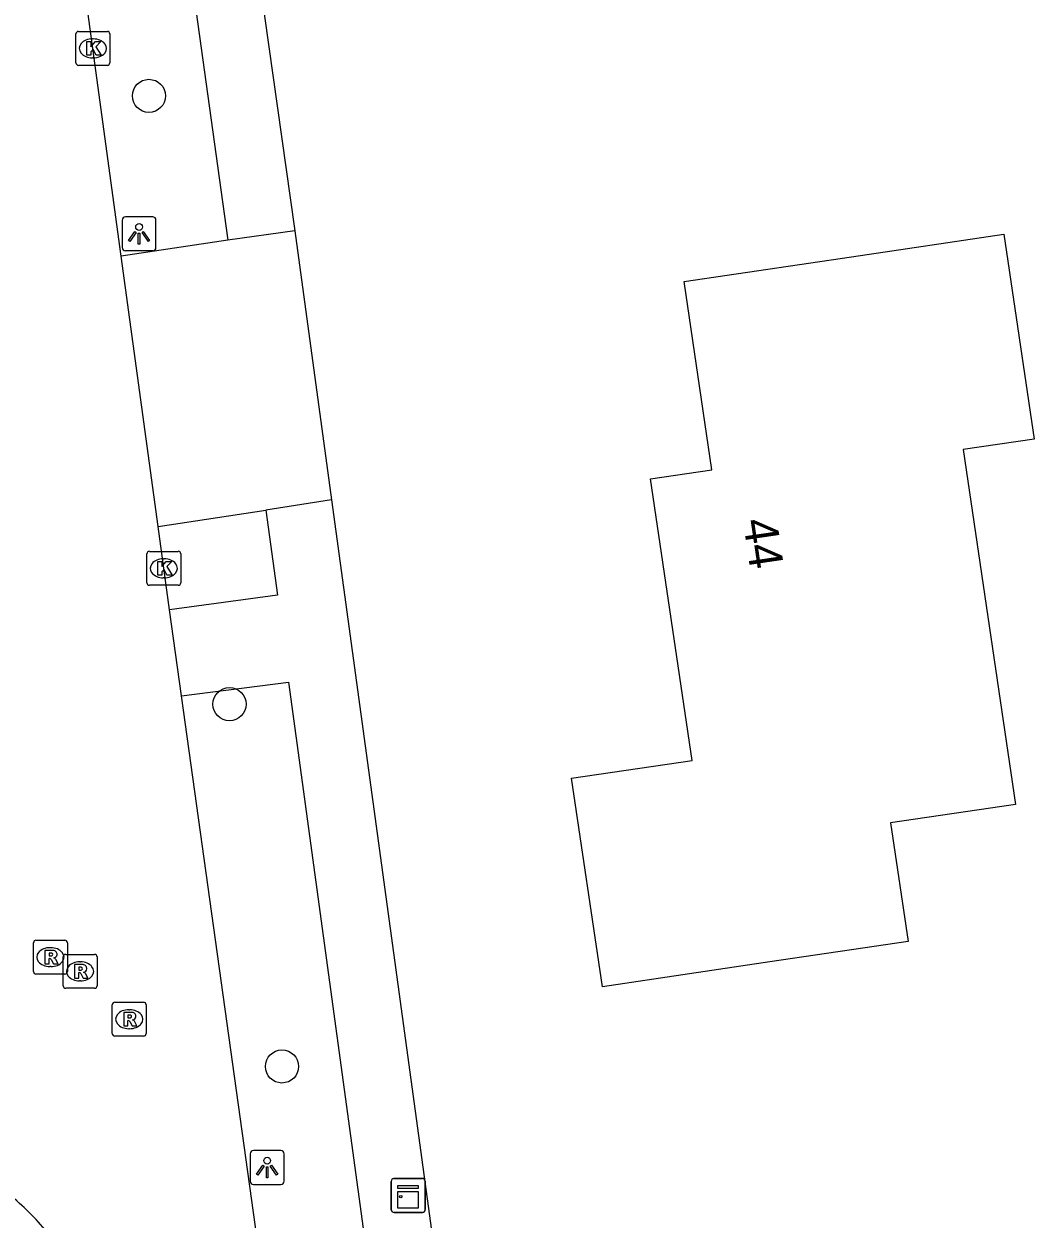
# Model space of a CAD drawing. Extents: x 162722 to 165099, y 384721 to 386283.
# Drawn here: x 164101.93 to 164131.75, y 385084.27 to 385119.55 of the extents above; entities that cross this region are included whole.
import ezdxf

# ---------------------------------------------------------------- set-up
doc = ezdxf.new("R2010")
doc.units = 0
for name, color, linetype in [('IMGEO_Boom', 7, 'Continuous'), ('IMGEO_Kast', 7, 'Continuous'), ('IMGEO_Kolk', 7, 'Continuous'), ('IMGEO_Lichtpunt', 7, 'Continuous'), ('IMGEO_Pand', 7, 'Continuous'), ('IMGEO_Pand_nummerreeks', 7, 'Continuous'), ('IMGEO_Rijbaan_lokaal_open', 7, 'Continuous'), ('IMGEO_Rioolput', 7, 'Continuous'), ('IMGEO_Voetpad_open', 7, 'Continuous')]:
    doc.layers.add(name, color=color, linetype=linetype)

msp = doc.modelspace()

# ---------------------------------------------------------------- linework, layer by layer
at = {"layer": 'IMGEO_Boom'}
for centre in [(164105.622, 385117.421), (164108, 385099.47), (164109.549, 385088.779)]:
    msp.add_circle(centre, 0.489, dxfattribs=at)
at = {"layer": 'IMGEO_Kast'}
for p, q in [((164112.775, 385084.546), (164112.775, 385085.387)), ((164112.775, 385085.387), (164112.775, 385084.546)), ((164112.85, 385085.471), (164113.691, 385085.471)), ((164113.691, 385085.471), (164112.85, 385085.471)), ((164113.775, 385085.396), (164113.775, 385084.555)), ((164113.775, 385084.555), (164113.775, 385085.396)), ((164113.7, 385084.471), (164112.859, 385084.471)), ((164112.859, 385084.471), (164113.7, 385084.471))]:
    msp.add_line(p, q, dxfattribs=at)
for points in [[(164112.97, 385085.261), (164113.57, 385085.261), (164113.57, 385085.176), (164112.97, 385085.176), (164112.97, 385085.261)], [(164112.97, 385085.086), (164113.57, 385085.086), (164113.57, 385084.597), (164112.97, 385084.597), (164112.97, 385085.086)]]:
    msp.add_lwpolyline(points, dxfattribs=at)
msp.add_circle((164113.054, 385084.935), 0.0377, dxfattribs=at)
for centre, start, end in [((164112.853, 385085.393), 92.4484, 184.2845), ((164112.853, 385085.393), 92.4484, 184.2845), ((164113.697, 385085.393), 2.4484, 94.2845), ((164113.697, 385085.393), 2.4484, 94.2845), ((164112.853, 385084.549), 182.4484, 274.2845), ((164112.853, 385084.549), 182.4484, 274.2845), ((164113.697, 385084.549), 272.4484, 4.2845), ((164113.697, 385084.549), 272.4484, 4.2845)]:
    msp.add_arc(centre, 0.0779, start, end, dxfattribs=at)
at = {"layer": 'IMGEO_Kolk'}
for p, q in [((164103.467, 385118.397), (164103.467, 385119.249)), ((164103.542, 385119.323), (164104.394, 385119.323)), ((164104.468, 385119.249), (164104.468, 385118.397)), ((164103.955, 385119.103), (164103.98, 385119.103)), ((164103.978, 385118.543), (164103.953, 385118.543)), ((164104.394, 385118.323), (164103.542, 385118.323)), ((164105.56, 385103.054), (164105.56, 385103.906)), ((164105.635, 385103.98), (164106.487, 385103.98)), ((164106.048, 385103.76), (164106.073, 385103.76)), ((164106.561, 385103.906), (164106.561, 385103.054)), ((164106.487, 385102.98), (164105.635, 385102.98)), ((164106.071, 385103.2), (164106.046, 385103.2))]:
    msp.add_line(p, q, dxfattribs=at)
for points in [[(164103.467, 385118.397), (164103.467, 385119.249)], [(164103.542, 385119.323), (164104.394, 385119.323)], [(164104.468, 385119.249), (164104.468, 385118.397)], [(164103.788, 385119.023), (164103.911, 385119.023), (164103.911, 385118.872), (164104.041, 385119.023), (164104.205, 385119.023), (164104.059, 385118.872), (164104.212, 385118.623), (164104.06, 385118.623), (164103.975, 385118.787), (164103.911, 385118.72), (164103.911, 385118.623), (164103.788, 385118.623), (164103.788, 385119.023)], [(164104.394, 385118.323), (164103.542, 385118.323)], [(164105.56, 385103.054), (164105.56, 385103.906)], [(164105.635, 385103.98), (164106.487, 385103.98)], [(164105.881, 385103.68), (164106.004, 385103.68), (164106.004, 385103.529), (164106.134, 385103.68), (164106.298, 385103.68), (164106.152, 385103.529), (164106.305, 385103.28), (164106.153, 385103.28), (164106.068, 385103.444), (164106.004, 385103.377), (164106.004, 385103.28), (164105.881, 385103.28), (164105.881, 385103.68)], [(164106.561, 385103.906), (164106.561, 385103.054)], [(164106.487, 385102.98), (164105.635, 385102.98)]]:
    msp.add_lwpolyline(points, dxfattribs=at)
for centre, start, end in [((164103.544, 385119.247), 91.552, 178.448), ((164103.544, 385119.247), 91.552, 178.448), ((164104.392, 385119.247), 1.552, 88.448), ((164104.392, 385119.247), 1.552, 88.448), ((164103.544, 385118.399), 181.552, 268.448), ((164103.544, 385118.399), 181.552, 268.448), ((164104.392, 385118.399), 271.552, 358.448), ((164104.392, 385118.399), 271.552, 358.448), ((164105.637, 385103.904), 91.552, 178.448), ((164105.637, 385103.904), 91.552, 178.448), ((164106.485, 385103.904), 1.552, 88.448), ((164106.485, 385103.904), 1.552, 88.448), ((164105.637, 385103.056), 181.552, 268.448), ((164105.637, 385103.056), 181.552, 268.448), ((164106.485, 385103.056), 271.552, 358.448), ((164106.485, 385103.056), 271.552, 358.448)]:
    msp.add_arc(centre, 0.0765, start, end, dxfattribs=at)
for centre, major_axis, ratio, start_param, end_param in [((164103.954, 385118.823), (-0.387, 0.002), 0.722429, 4.712389, 7.853982), ((164103.979, 385118.823), (-0.39, 0.002), 0.717154, 1.570796, 4.712389), ((164106.047, 385103.48), (-0.387, 0.002), 0.722429, 4.712389, 7.853982), ((164106.072, 385103.48), (-0.39, 0.002), 0.717154, 1.570796, 4.712389)]:
    msp.add_ellipse(centre, major_axis=major_axis, ratio=ratio, start_param=start_param, end_param=end_param, dxfattribs=at)
at = {"layer": 'IMGEO_Lichtpunt'}
for p, q in [((164104.832, 385113.755), (164104.832, 385112.948)), ((164104.832, 385113.755), (164104.832, 385112.948)), ((164105.734, 385113.85), (164104.926, 385113.85)), ((164105.734, 385113.85), (164104.926, 385113.85)), ((164105.828, 385112.948), (164105.828, 385113.755)), ((164105.828, 385112.948), (164105.828, 385113.755)), ((164104.926, 385112.854), (164105.734, 385112.854)), ((164104.926, 385112.854), (164105.734, 385112.854)), ((164108.613, 385086.2), (164108.613, 385085.393)), ((164108.613, 385086.2), (164108.613, 385085.393)), ((164109.515, 385086.295), (164108.707, 385086.295)), ((164109.515, 385086.295), (164108.707, 385086.295)), ((164109.609, 385085.393), (164109.609, 385086.2)), ((164109.609, 385085.393), (164109.609, 385086.2)), ((164108.707, 385085.299), (164109.515, 385085.299)), ((164108.707, 385085.299), (164109.515, 385085.299))]:
    msp.add_line(p, q, dxfattribs=at)
for points in [[(164105.206, 385113.419), (164105.245, 385113.391), (164105.057, 385113.129), (164105.019, 385113.156), (164105.206, 385113.419)], [(164105.308, 385113.371), (164105.355, 385113.371), (164105.355, 385113.049), (164105.308, 385113.049), (164105.308, 385113.371)], [(164105.418, 385113.391), (164105.456, 385113.418), (164105.643, 385113.156), (164105.604, 385113.128), (164105.418, 385113.391)], [(164108.987, 385085.864), (164109.026, 385085.836), (164108.838, 385085.574), (164108.8, 385085.601), (164108.987, 385085.864)], [(164109.089, 385085.816), (164109.136, 385085.816), (164109.136, 385085.494), (164109.089, 385085.494), (164109.089, 385085.816)], [(164109.199, 385085.836), (164109.237, 385085.863), (164109.424, 385085.601), (164109.385, 385085.573), (164109.199, 385085.836)]]:
    msp.add_lwpolyline(points, dxfattribs=at)
for centre in [(164105.331, 385113.553), (164109.112, 385085.998)]:
    msp.add_circle(centre, 0.0994, dxfattribs=at)
for centre, start, end in [((164104.926, 385113.755), 90, 180), ((164104.926, 385113.755), 90, 180), ((164105.734, 385113.755), 0, 90), ((164105.734, 385113.755), 0, 90), ((164104.926, 385112.948), 180, 270), ((164104.926, 385112.948), 180, 270), ((164105.734, 385112.948), 270, 0), ((164105.734, 385112.948), 270, 360), ((164108.707, 385086.2), 90, 180), ((164108.707, 385086.2), 90, 180), ((164109.515, 385086.2), 0, 90), ((164109.515, 385086.2), 0, 90), ((164108.707, 385085.393), 180, 270), ((164108.707, 385085.393), 180, 270), ((164109.515, 385085.393), 270, 0), ((164109.515, 385085.393), 270, 360)]:
    msp.add_arc(centre, 0.0946, start, end, dxfattribs=at)
at = {"layer": 'IMGEO_Pand'}
msp.add_lwpolyline([(164118.098, 385097.284), (164121.653, 385097.809), (164120.426, 385106.121), (164122.237, 385106.388), (164121.417, 385111.942), (164126.364, 385112.672), (164130.858, 385113.336), (164131.75, 385107.292), (164129.656, 385106.983), (164131.203, 385096.51), (164127.512, 385095.965), (164128.029, 385092.464), (164123.953, 385091.862), (164119.006, 385091.132), (164118.098, 385097.284)], dxfattribs=at)
at = {"layer": 'IMGEO_Rijbaan_lokaal_open'}
for points in [[(164104.802, 385112.693), (164102.809, 385127.339)], [(164105.897, 385104.717), (164104.802, 385112.693)], [(164106.23, 385102.25), (164106.061, 385103.48), (164105.897, 385104.717)], [(164106.583, 385099.714), (164106.23, 385102.25)], [(164109.468, 385078.814), (164109.099, 385081.644), (164106.583, 385099.714)]]:
    msp.add_lwpolyline(points, dxfattribs=at)
msp.add_arc((164095.292, 385077.685), 9.601, 39.0574, 48.5439, dxfattribs=at)
at = {"layer": 'IMGEO_Rioolput'}
for p, q in [((164102.213, 385091.578), (164102.213, 385092.43)), ((164102.288, 385092.504), (164103.14, 385092.504)), ((164103.214, 385092.43), (164103.214, 385091.578)), ((164102.701, 385092.284), (164102.726, 385092.284)), ((164103.165, 385092.085), (164104.017, 385092.085)), ((164102.724, 385091.724), (164102.699, 385091.724)), ((164103.09, 385091.159), (164103.09, 385092.011)), ((164103.578, 385091.865), (164103.603, 385091.865)), ((164104.091, 385092.011), (164104.091, 385091.159)), ((164103.14, 385091.504), (164102.288, 385091.504)), ((164104.017, 385091.085), (164103.165, 385091.085)), ((164103.601, 385091.305), (164103.576, 385091.305)), ((164104.614, 385090.673), (164105.466, 385090.673)), ((164104.539, 385089.747), (164104.539, 385090.599)), ((164105.027, 385090.453), (164105.052, 385090.453)), ((164105.54, 385090.599), (164105.54, 385089.747)), ((164105.466, 385089.673), (164104.614, 385089.673)), ((164105.05, 385089.893), (164105.025, 385089.893))]:
    msp.add_line(p, q, dxfattribs=at)
for points in [[(164102.213, 385091.578), (164102.213, 385092.43)], [(164102.288, 385092.504), (164103.14, 385092.504)], [(164103.214, 385092.43), (164103.214, 385091.578)], [(164102.802, 385092.202), (164102.55, 385092.204), (164102.55, 385091.804)], [(164102.728, 385092.123), (164102.674, 385092.123), (164102.674, 385092.042)], [(164102.674, 385092.042), (164102.726, 385092.042)], [(164103.165, 385092.085), (164104.017, 385092.085)], [(164102.55, 385091.804), (164102.674, 385091.804), (164102.674, 385091.966), (164102.685, 385091.966)], [(164102.732, 385091.937), (164102.803, 385091.804), (164102.943, 385091.804), (164102.878, 385091.93)], [(164103.09, 385091.159), (164103.09, 385092.011)], [(164103.679, 385091.783), (164103.427, 385091.785), (164103.427, 385091.385)], [(164103.605, 385091.704), (164103.551, 385091.704), (164103.551, 385091.623)], [(164104.091, 385092.011), (164104.091, 385091.159)], [(164103.14, 385091.504), (164102.288, 385091.504)], [(164103.427, 385091.385), (164103.551, 385091.385), (164103.551, 385091.547), (164103.562, 385091.547)], [(164103.551, 385091.623), (164103.603, 385091.623)], [(164103.609, 385091.518), (164103.68, 385091.385), (164103.82, 385091.385), (164103.755, 385091.511)], [(164104.017, 385091.085), (164103.165, 385091.085)], [(164104.614, 385090.673), (164105.466, 385090.673)], [(164104.539, 385089.747), (164104.539, 385090.599)], [(164105.128, 385090.371), (164104.876, 385090.373), (164104.876, 385089.973)], [(164105.054, 385090.292), (164105, 385090.292), (164105, 385090.211)], [(164105.54, 385090.599), (164105.54, 385089.747)], [(164104.876, 385089.973), (164105, 385089.973), (164105, 385090.135), (164105.011, 385090.135)], [(164105, 385090.211), (164105.052, 385090.211)], [(164105.058, 385090.106), (164105.129, 385089.973), (164105.269, 385089.973), (164105.204, 385090.099)], [(164105.466, 385089.673), (164104.614, 385089.673)]]:
    msp.add_lwpolyline(points, dxfattribs=at)
for centre, radius, start, end in [((164102.29, 385092.428), 0.0765, 91.552, 178.448), ((164102.29, 385092.428), 0.0765, 91.552, 178.448), ((164103.138, 385092.428), 0.0765, 1.552, 88.448), ((164103.138, 385092.428), 0.0765, 1.552, 88.448), ((164102.71, 385092.231), 0.19, 274.7715, 282.9687), ((164102.734, 385092.027), 0.0964, 77.0061, 93.1865), ((164102.748, 385092.084), 0.0378, 276.6634, 79.6772), ((164102.801, 385092.092), 0.109, 350.3612, 89.416), ((164102.799, 385092.092), 0.112, 277.5842, 350.9817), ((164103.167, 385092.009), 0.0765, 91.552, 178.448), ((164103.167, 385092.009), 0.0765, 91.552, 178.448), ((164104.015, 385092.009), 0.0765, 1.552, 88.448), ((164104.015, 385092.009), 0.0765, 1.552, 88.448), ((164102.684, 385091.913), 0.0533, 26.0293, 88.6989), ((164102.783, 385091.877), 0.108, 29.5134, 73.7905), ((164103.611, 385091.608), 0.0964, 77.0061, 93.1865), ((164103.625, 385091.665), 0.0378, 276.6634, 79.6772), ((164103.678, 385091.673), 0.109, 350.3612, 89.416), ((164102.29, 385091.58), 0.0765, 181.552, 268.448), ((164102.29, 385091.58), 0.0765, 181.552, 268.448), ((164103.138, 385091.58), 0.0765, 271.552, 358.448), ((164103.138, 385091.58), 0.0765, 271.552, 358.448), ((164103.561, 385091.494), 0.0533, 26.0293, 88.6989), ((164103.587, 385091.812), 0.19, 274.7715, 282.9687), ((164103.676, 385091.673), 0.112, 277.5842, 350.9817), ((164103.66, 385091.458), 0.108, 29.5134, 73.7905), ((164103.167, 385091.161), 0.0765, 181.552, 268.448), ((164103.167, 385091.161), 0.0765, 181.552, 268.448), ((164104.015, 385091.161), 0.0765, 271.552, 358.448), ((164104.015, 385091.161), 0.0765, 271.552, 358.448), ((164104.616, 385090.597), 0.0765, 91.552, 178.448), ((164104.616, 385090.597), 0.0765, 91.552, 178.448), ((164105.464, 385090.597), 0.0765, 1.552, 88.448), ((164105.464, 385090.597), 0.0765, 1.552, 88.448), ((164105.06, 385090.196), 0.0964, 77.0061, 93.1865), ((164105.074, 385090.253), 0.0378, 276.6634, 79.6772), ((164105.127, 385090.261), 0.109, 350.3612, 89.416), ((164105.01, 385090.082), 0.0533, 26.0293, 88.6989), ((164105.036, 385090.4), 0.19, 274.7715, 282.9687), ((164105.125, 385090.261), 0.112, 277.5842, 350.9817), ((164105.109, 385090.046), 0.108, 29.5134, 73.7905), ((164104.616, 385089.749), 0.0765, 181.552, 268.448), ((164104.616, 385089.749), 0.0765, 181.552, 268.448), ((164105.464, 385089.749), 0.0765, 271.552, 358.448), ((164105.464, 385089.749), 0.0765, 271.552, 358.448)]:
    msp.add_arc(centre, radius, start, end, dxfattribs=at)
for centre, major_axis, ratio, start_param, end_param in [((164102.7, 385092.004), (-0.387, 0.002), 0.722429, 4.712389, 7.853982), ((164102.725, 385092.004), (-0.39, 0.002), 0.717154, 1.570796, 4.712389), ((164103.577, 385091.585), (-0.387, 0.002), 0.722429, 4.712389, 7.853982), ((164103.602, 385091.585), (-0.39, 0.002), 0.717154, 1.570796, 4.712389), ((164105.026, 385090.173), (-0.387, 0.002), 0.722429, 4.712389, 7.853982), ((164105.051, 385090.173), (-0.39, 0.002), 0.717154, 1.570796, 4.712389)]:
    msp.add_ellipse(centre, major_axis=major_axis, ratio=ratio, start_param=start_param, end_param=end_param, dxfattribs=at)
at = {"layer": 'IMGEO_Voetpad_open'}
for points in [[(164107.861, 385128.069), (164109.929, 385113.435)], [(164105.927, 385127.762), (164107.954, 385113.16)], [(164109.929, 385113.435), (164107.954, 385113.16)], [(164109.929, 385113.435), (164111.013, 385105.498)], [(164107.954, 385113.16), (164104.802, 385112.693)], [(164111.013, 385105.498), (164109.069, 385105.197)], [(164111.013, 385105.498), (164114.568, 385079.483)], [(164105.897, 385104.717), (164109.069, 385105.197)], [(164109.069, 385105.197), (164109.418, 385102.686), (164106.23, 385102.25)], [(164106.583, 385099.714), (164109.746, 385100.117), (164112.597, 385079.241)]]:
    msp.add_lwpolyline(points, dxfattribs=at)

# ---------------------------------------------------------------- texts
at = {"layer": 'IMGEO_Pand_nummerreeks'}
msp.add_text('44', height=1, rotation=278.3972, dxfattribs=at).set_placement((164123.155, 385104.887))

doc.saveas('drawing.dxf')
